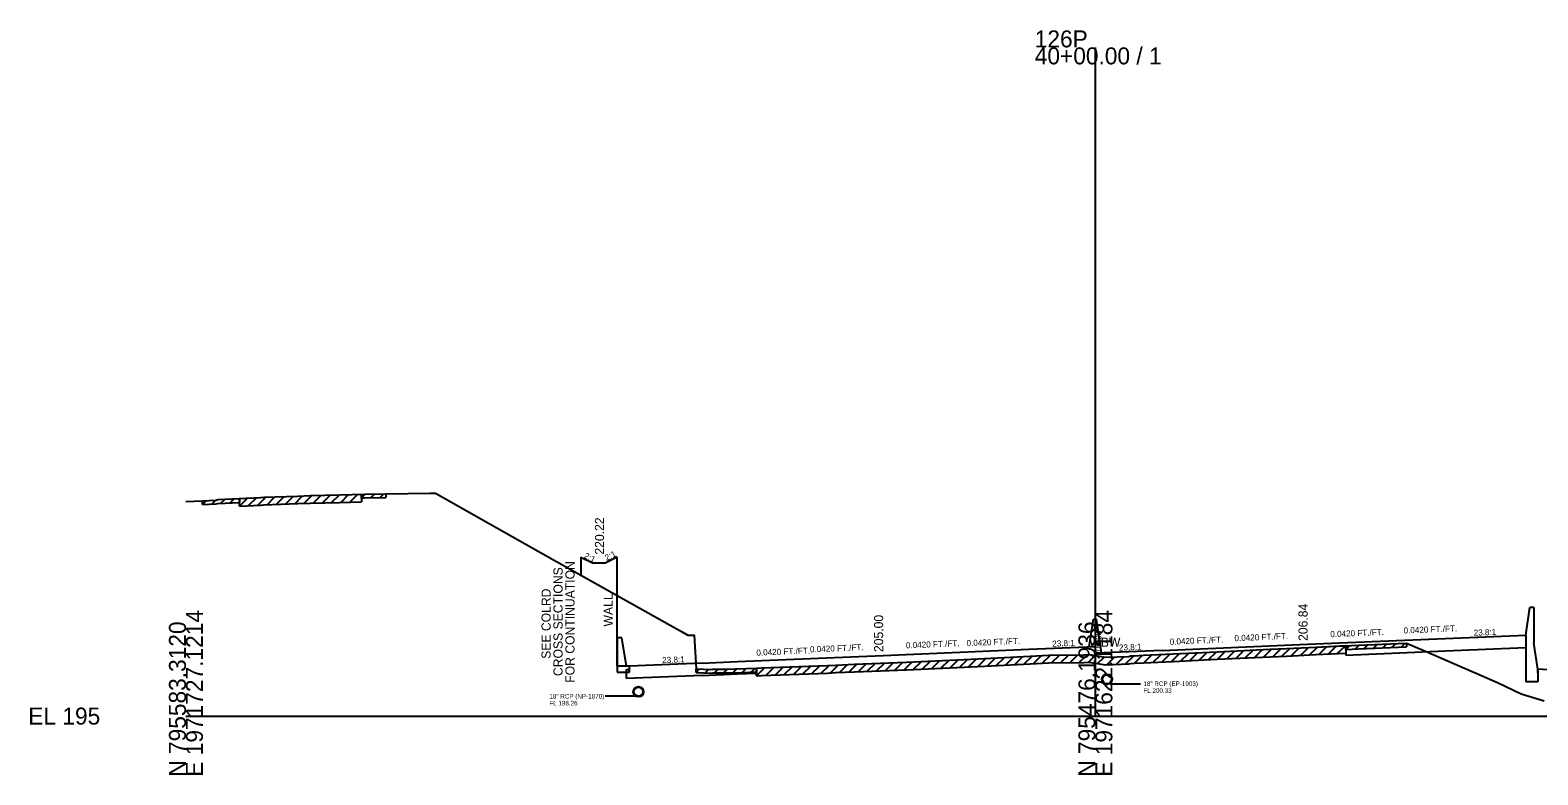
# Model space of a CAD drawing. Extents: x -161 to 1970889, y -4362 to 797231.
# Drawn here: x 974.3 to 1223, y 2490.3 to 2613.1 of the extents above; entities that cross this region are included whole.
import ezdxf

# ---------------------------------------------------------------- set-up
doc = ezdxf.new("R2010")
doc.units = 0
for name, color, linetype in [('RD_GPK_XS_Cell', 7, 'Continuous'), ('RD_XS_Base', 7, 'Continuous'), ('RD_XS_Box', 7, 'Continuous'), ('RD_XS_ExGround', 7, 'Continuous'), ('RD_XS_ExPaveRet', 7, 'Continuous'), ('RD_XS_MedBWall', 7, 'Continuous'), ('RD_XS_Misc_Line', 7, 'Continuous'), ('RD_XS_Pave', 7, 'Continuous'), ('RD_XS_PaveOvlay', 7, 'Continuous'), ('RD_XS_PaveShd', 7, 'Continuous'), ('RD_XS_Pipe', 7, 'Continuous'), ('RD_XS_TieSlope', 7, 'Continuous'), ('RD_XS_TX_Elev_EX', 7, 'Continuous'), ('RD_XS_TX_Elev_PR', 7, 'Continuous'), ('RD_XS_TX_Misc', 7, 'Continuous'), ('RD_XS_TX_MkPT', 7, 'Continuous'), ('RD_XS_TX_Notes', 7, 'Continuous'), ('RD_XS_TX_Profile', 7, 'Continuous'), ('RD_XS_TX_Slope', 7, 'Continuous')]:
    doc.layers.add(name, color=color, linetype=linetype)

msp = doc.modelspace()

# ---------------------------------------------------------------- linework, layer by layer
at = {"layer": 'RD_GPK_XS_Cell'}
for p, q in [((1150, 2500), (1150, 2610.28)), ((1000, 2500), (1150, 2500)), ((1150, 2500), (1300, 2500))]:
    msp.add_line(p, q, dxfattribs=at)
at = {"layer": 'RD_XS_Base'}
for p, q in [((1191.31, 2510.07), (1209, 2510.81)), ((1209, 2510.81), (1221, 2511.32)), ((1072.65, 2507.66), (1073.15, 2507.69)), ((1072.65, 2506.18), (1072.65, 2507.66)), ((1085.16, 2506.71), (1072.65, 2506.18)), ((1073.15, 2507.69), (1073.15, 2508.25)), ((1085.16, 2506.71), (1091, 2506.96)), ((1091, 2506.96), (1094.13, 2507.09)), ((1222.98, 2507.15), (1222.98, 2507.71))]:
    msp.add_line(p, q, dxfattribs=at)
at = {"layer": 'RD_XS_Box'}
for p, q in [((1071.15, 2508.25), (1071.15, 2526.22)), ((1073.15, 2508.25), (1071.15, 2508.25))]:
    msp.add_line(p, q, dxfattribs=at)
at = {"layer": 'RD_XS_ExGround'}
msp.add_lwpolyline([(1000, 2535.38), (1002.74, 2535.49), (1004.91, 2535.61), (1005.28, 2535.69), (1012.31, 2536.06), (1012.83, 2536.09), (1018.44, 2536.29), (1020.51, 2536.36), (1025.32, 2536.49), (1029.45, 2536.6), (1032.97, 2536.65), (1040.23, 2536.76), (1040.86, 2536.76), (1041.16, 2536.75), (1052.53, 2530.34), (1060.65, 2525.75), (1081.74, 2513.94), (1082.77, 2513.36), (1083.82, 2513.36), (1084.13, 2507.81), (1086.6, 2507.69), (1086.92, 2507.73), (1089.09, 2507.75), (1090.65, 2507.77), (1094.23, 2507.9), (1094.95, 2507.93), (1105.84, 2508.35), (1107.2, 2508.41), (1110.25, 2508.54), (1118.83, 2508.9), (1128.37, 2509.32), (1130.63, 2509.42), (1139.26, 2509.86), (1142.34, 2510.02), (1145.11, 2510.08), (1145.43, 2510.04), (1148.11, 2510.11), (1148.99, 2510.13), (1149.54, 2510.05), (1150, 2509.98), (1151.65, 2509.71), (1155.51, 2509.85), (1155.78, 2509.93), (1156.45, 2509.96), (1157.91, 2510.04), (1162.82, 2510.27), (1170.07, 2510.61), (1178.83, 2511.03), (1181.53, 2511.15), (1186.35, 2511.38), (1193.42, 2511.71), (1199.94, 2511.98), (1201.31, 2512.04), (1204.18, 2510.8), (1216.33, 2505.56), (1220.21, 2503.67), (1224.04, 2502.52)], dxfattribs=at)
at = {"layer": 'RD_XS_ExPaveRet'}
for p, q in [((1028.94, 2536.58), (1028.94, 2535.33)), ((1028.94, 2535.96), (1028.94, 2536.58)), ((1028.94, 2536.58), (1028.94, 2535.33)), ((1028.94, 2535.96), (1028.94, 2536.58)), ((1028.94, 2536.58), (1028.94, 2535.33)), ((1028.94, 2535.96), (1028.94, 2536.58)), ((1032.97, 2536.65), (1032.97, 2536.02)), ((1032.97, 2536.65), (1032.97, 2536.02)), ((1032.97, 2536.65), (1032.97, 2536.02)), ((1002.74, 2534.87), (1002.74, 2535.49)), ((1002.74, 2534.87), (1002.74, 2535.49)), ((1002.74, 2534.87), (1002.74, 2535.49)), ((1002.74, 2534.87), (1004.91, 2534.98)), ((1002.74, 2534.87), (1004.91, 2534.98)), ((1002.74, 2534.87), (1004.91, 2534.98)), ((1004.91, 2534.98), (1005.28, 2535.06)), ((1004.91, 2534.98), (1005.28, 2535.06)), ((1004.91, 2534.98), (1005.28, 2535.06)), ((1005.28, 2535.06), (1008.82, 2535.25)), ((1005.28, 2535.06), (1008.82, 2535.25)), ((1005.28, 2535.06), (1008.82, 2535.25)), ((1008.82, 2534.63), (1008.82, 2535.88)), ((1008.82, 2535.88), (1008.82, 2535.25)), ((1008.82, 2534.63), (1008.82, 2535.88)), ((1008.82, 2535.88), (1008.82, 2535.25)), ((1008.82, 2534.63), (1008.82, 2535.88)), ((1008.82, 2535.88), (1008.82, 2535.25)), ((1008.82, 2534.63), (1012.31, 2534.81)), ((1008.82, 2534.63), (1012.31, 2534.81)), ((1008.82, 2534.63), (1012.31, 2534.81)), ((1012.31, 2534.81), (1012.83, 2534.84)), ((1012.31, 2534.81), (1012.83, 2534.84)), ((1012.31, 2534.81), (1012.83, 2534.84)), ((1012.83, 2534.84), (1018.44, 2535.04)), ((1012.83, 2534.84), (1018.44, 2535.04)), ((1012.83, 2534.84), (1018.44, 2535.04)), ((1018.44, 2535.04), (1020.51, 2535.11)), ((1018.44, 2535.04), (1020.51, 2535.11)), ((1018.44, 2535.04), (1020.51, 2535.11)), ((1020.51, 2535.11), (1025.32, 2535.24)), ((1020.51, 2535.11), (1025.32, 2535.24)), ((1020.51, 2535.11), (1025.32, 2535.24)), ((1025.32, 2535.24), (1028.94, 2535.33)), ((1025.32, 2535.24), (1028.94, 2535.33)), ((1025.32, 2535.24), (1028.94, 2535.33)), ((1028.94, 2535.96), (1029.45, 2535.97)), ((1028.94, 2535.96), (1029.45, 2535.97)), ((1028.94, 2535.96), (1029.45, 2535.97)), ((1029.45, 2535.97), (1032.97, 2536.02)), ((1029.45, 2535.97), (1032.97, 2536.02)), ((1029.45, 2535.97), (1032.97, 2536.02)), ((1191.31, 2511.62), (1191.31, 2510.37)), ((1191.31, 2510.99), (1191.31, 2511.62)), ((1201.31, 2512.04), (1201.31, 2511.41)), ((1162.82, 2509.02), (1170.07, 2509.36)), ((1170.07, 2509.36), (1178.83, 2509.78)), ((1178.83, 2509.78), (1181.53, 2509.9)), ((1181.53, 2509.9), (1186.35, 2510.13)), ((1186.35, 2510.13), (1191.31, 2510.37)), ((1191.31, 2510.99), (1193.42, 2511.09)), ((1193.42, 2511.09), (1199.94, 2511.36)), ((1199.94, 2511.36), (1201.31, 2511.41)), ((1084.13, 2507.19), (1084.13, 2507.81)), ((1084.13, 2507.19), (1086.6, 2507.07)), ((1086.6, 2507.07), (1086.92, 2507.11)), ((1086.92, 2507.11), (1089.09, 2507.13)), ((1089.09, 2507.13), (1090.65, 2507.14)), ((1090.65, 2507.14), (1094.13, 2507.27)), ((1094.13, 2506.65), (1094.13, 2507.9)), ((1094.13, 2507.9), (1094.13, 2507.27)), ((1094.13, 2506.65), (1094.23, 2506.65)), ((1094.23, 2506.65), (1094.95, 2506.68)), ((1094.95, 2506.68), (1105.84, 2507.1)), ((1105.84, 2507.1), (1107.2, 2507.16)), ((1107.2, 2507.16), (1110.25, 2507.29)), ((1110.25, 2507.29), (1118.83, 2507.65)), ((1118.83, 2507.65), (1128.37, 2508.07)), ((1128.37, 2508.07), (1130.63, 2508.17)), ((1130.63, 2508.17), (1139.26, 2508.61)), ((1139.26, 2508.61), (1142.34, 2508.77)), ((1142.34, 2508.77), (1145.11, 2508.83)), ((1145.11, 2508.83), (1145.43, 2508.79)), ((1145.43, 2508.79), (1148.11, 2508.86)), ((1148.11, 2508.86), (1148.99, 2508.88)), ((1148.99, 2508.88), (1149.54, 2508.8)), ((1149.54, 2508.8), (1150, 2508.73)), ((1150, 2508.73), (1151.65, 2508.46)), ((1151.65, 2508.46), (1155.51, 2508.6)), ((1155.51, 2508.6), (1155.78, 2508.68)), ((1155.78, 2508.68), (1156.45, 2508.71)), ((1156.45, 2508.71), (1157.91, 2508.79)), ((1157.91, 2508.79), (1162.82, 2509.02))]:
    msp.add_line(p, q, dxfattribs=at)
at = {"layer": 'RD_XS_MedBWall'}
for p, q in [((1221, 2513.36), (1221.67, 2517.9)), ((1222.33, 2517.9), (1221.67, 2517.9)), ((1222.33, 2517.9), (1222.33, 2512.1)), ((1149, 2511.43), (1149.67, 2515.97)), ((1149.67, 2515.97), (1150.17, 2515.97)), ((1151, 2510.42), (1150.17, 2515.97)), ((1071.9, 2512.91), (1071.15, 2512.91)), ((1071.15, 2512.91), (1071.15, 2507.25)), ((1072.65, 2508.25), (1071.9, 2512.91)), ((1221, 2513.36), (1221, 2511.32)), ((1221, 2513.36), (1221, 2505.67)), ((1222.98, 2507.71), (1222.33, 2512.1)), ((1071.15, 2507.25), (1073.15, 2507.25)), ((1073.15, 2508.25), (1072.65, 2508.25)), ((1073.15, 2507.25), (1073.15, 2508.25)), ((1222.98, 2507.71), (1222.98, 2505.67)), ((1222.98, 2505.67), (1221, 2505.67))]:
    msp.add_line(p, q, dxfattribs=at)
at = {"layer": 'RD_XS_Misc_Line'}
for p, q in [((1022.5, 2535.17), (1023.8, 2536.45)), ((1022.5, 2535.17), (1023.8, 2536.45)), ((1022.5, 2535.17), (1023.8, 2536.45)), ((1024.02, 2535.21), (1025.32, 2536.49)), ((1024.02, 2535.21), (1025.32, 2536.49)), ((1024.02, 2535.21), (1025.32, 2536.49)), ((1025.54, 2535.25), (1026.84, 2536.53)), ((1025.54, 2535.25), (1026.84, 2536.53)), ((1025.54, 2535.25), (1026.84, 2536.53)), ((1027.06, 2535.29), (1028.36, 2536.57)), ((1027.06, 2535.29), (1028.36, 2536.57)), ((1027.06, 2535.29), (1028.36, 2536.57)), ((1028.94, 2535.96), (1029.58, 2536.6)), ((1028.94, 2535.96), (1029.58, 2536.6)), ((1028.94, 2535.96), (1029.58, 2536.6)), ((1030.46, 2535.99), (1031.1, 2536.62)), ((1030.46, 2535.99), (1031.1, 2536.62)), ((1030.46, 2535.99), (1031.1, 2536.62)), ((1031.98, 2536.01), (1032.62, 2536.64)), ((1031.98, 2536.01), (1032.62, 2536.64)), ((1031.98, 2536.01), (1032.62, 2536.64)), ((1002.74, 2534.87), (1003.41, 2535.53)), ((1002.74, 2534.87), (1003.41, 2535.53)), ((1002.74, 2534.87), (1003.41, 2535.53)), ((1004.26, 2534.95), (1004.93, 2535.61)), ((1004.26, 2534.95), (1004.93, 2535.61)), ((1004.26, 2534.95), (1004.93, 2535.61)), ((1005.78, 2535.09), (1006.45, 2535.75)), ((1005.78, 2535.09), (1006.45, 2535.75)), ((1005.78, 2535.09), (1006.45, 2535.75)), ((1007.3, 2535.17), (1007.97, 2535.83)), ((1007.3, 2535.17), (1007.97, 2535.83)), ((1007.3, 2535.17), (1007.97, 2535.83)), ((1008.82, 2534.63), (1010.16, 2535.95)), ((1008.82, 2534.63), (1010.16, 2535.95)), ((1008.82, 2534.63), (1010.16, 2535.95)), ((1010.34, 2534.71), (1011.68, 2536.03)), ((1010.34, 2534.71), (1011.68, 2536.03)), ((1010.34, 2534.71), (1011.68, 2536.03)), ((1011.86, 2534.79), (1013.19, 2536.1)), ((1011.86, 2534.79), (1013.19, 2536.1)), ((1011.86, 2534.79), (1013.19, 2536.1)), ((1013.38, 2534.86), (1014.69, 2536.16)), ((1013.38, 2534.86), (1014.69, 2536.16)), ((1013.38, 2534.86), (1014.69, 2536.16)), ((1014.9, 2534.91), (1016.21, 2536.21)), ((1014.9, 2534.91), (1016.21, 2536.21)), ((1014.9, 2534.91), (1016.21, 2536.21)), ((1016.42, 2534.97), (1017.73, 2536.27)), ((1016.42, 2534.97), (1017.73, 2536.27)), ((1016.42, 2534.97), (1017.73, 2536.27)), ((1017.94, 2535.02), (1019.25, 2536.32)), ((1017.94, 2535.02), (1019.25, 2536.32)), ((1017.94, 2535.02), (1019.25, 2536.32)), ((1019.46, 2535.08), (1020.77, 2536.37)), ((1019.46, 2535.08), (1020.77, 2536.37)), ((1019.46, 2535.08), (1020.77, 2536.37)), ((1020.98, 2535.13), (1022.28, 2536.41)), ((1020.98, 2535.13), (1022.28, 2536.41)), ((1020.98, 2535.13), (1022.28, 2536.41)), ((1189.9, 2510.3), (1191.23, 2511.61)), ((1191.31, 2510.99), (1191.98, 2511.65)), ((1192.83, 2511.06), (1193.5, 2511.72)), ((1194.35, 2511.13), (1195.01, 2511.78)), ((1195.87, 2511.19), (1196.53, 2511.84)), ((1197.39, 2511.25), (1198.05, 2511.91)), ((1198.91, 2511.32), (1199.57, 2511.97)), ((1200.43, 2511.38), (1201.09, 2512.03)), ((1123.01, 2507.83), (1124.34, 2509.14)), ((1124.53, 2507.9), (1125.86, 2509.21)), ((1126.05, 2507.97), (1127.38, 2509.28)), ((1127.57, 2508.03), (1128.9, 2509.34)), ((1129.09, 2508.1), (1130.42, 2509.42)), ((1130.61, 2508.17), (1131.95, 2509.49)), ((1132.13, 2508.25), (1133.47, 2509.57)), ((1133.65, 2508.33), (1134.99, 2509.64)), ((1135.17, 2508.4), (1136.51, 2509.72)), ((1136.69, 2508.48), (1138.03, 2509.8)), ((1138.21, 2508.56), (1139.55, 2509.87)), ((1139.73, 2508.63), (1141.07, 2509.95)), ((1141.25, 2508.71), (1142.58, 2510.02)), ((1142.77, 2508.77), (1144.07, 2510.05)), ((1144.29, 2508.81), (1145.54, 2510.04)), ((1145.81, 2508.8), (1147.12, 2510.09)), ((1147.33, 2508.84), (1148.63, 2510.12)), ((1148.85, 2508.88), (1149.97, 2509.98)), ((1150.37, 2508.66), (1151.46, 2509.74)), ((1151.89, 2508.47), (1153.21, 2509.77)), ((1153.41, 2508.52), (1154.73, 2509.82)), ((1154.94, 2508.58), (1156.33, 2509.96)), ((1156.46, 2508.71), (1157.79, 2510.03)), ((1157.98, 2508.79), (1159.31, 2510.1)), ((1159.5, 2508.86), (1160.83, 2510.18)), ((1161.02, 2508.93), (1162.35, 2510.25)), ((1162.54, 2509.01), (1163.87, 2510.32)), ((1164.06, 2509.08), (1165.39, 2510.39)), ((1165.58, 2509.15), (1166.91, 2510.46)), ((1167.1, 2509.22), (1168.43, 2510.54)), ((1168.62, 2509.3), (1169.95, 2510.61)), ((1170.14, 2509.37), (1171.47, 2510.68)), ((1171.66, 2509.44), (1172.99, 2510.75)), ((1173.18, 2509.51), (1174.51, 2510.82)), ((1174.7, 2509.58), (1176.03, 2510.89)), ((1176.22, 2509.65), (1177.55, 2510.96)), ((1177.74, 2509.72), (1179.07, 2511.04)), ((1179.26, 2509.79), (1180.59, 2511.11)), ((1180.78, 2509.86), (1182.11, 2511.18)), ((1182.3, 2509.94), (1183.63, 2511.25)), ((1183.82, 2510.01), (1185.15, 2511.32)), ((1185.34, 2510.08), (1186.67, 2511.4)), ((1186.86, 2510.16), (1188.19, 2511.47)), ((1188.38, 2510.23), (1189.71, 2511.54)), ((1084.13, 2507.19), (1084.73, 2507.78)), ((1085.65, 2507.11), (1086.25, 2507.71)), ((1087.17, 2507.11), (1087.81, 2507.74)), ((1088.69, 2507.13), (1089.33, 2507.76)), ((1090.21, 2507.14), (1090.85, 2507.77)), ((1091.73, 2507.18), (1092.39, 2507.83)), ((1093.25, 2507.24), (1093.91, 2507.89)), ((1094.13, 2506.65), (1095.45, 2507.95)), ((1095.65, 2506.71), (1096.97, 2508.01)), ((1097.17, 2506.77), (1098.49, 2508.07)), ((1098.69, 2506.83), (1100.01, 2508.13)), ((1100.21, 2506.88), (1101.53, 2508.19)), ((1101.73, 2506.94), (1103.05, 2508.25)), ((1103.25, 2507), (1104.57, 2508.31)), ((1104.77, 2507.06), (1106.09, 2508.36)), ((1106.29, 2507.12), (1107.61, 2508.43)), ((1107.81, 2507.19), (1109.13, 2508.49)), ((1109.33, 2507.25), (1110.65, 2508.56)), ((1110.85, 2507.32), (1112.17, 2508.62)), ((1112.37, 2507.38), (1113.69, 2508.69)), ((1113.89, 2507.44), (1115.21, 2508.75)), ((1115.41, 2507.51), (1116.73, 2508.81)), ((1116.93, 2507.57), (1118.25, 2508.88)), ((1118.45, 2507.63), (1119.78, 2508.94)), ((1119.97, 2507.7), (1121.3, 2509.01)), ((1121.49, 2507.77), (1122.82, 2509.08))]:
    msp.add_line(p, q, dxfattribs=at)
at = {"layer": 'RD_XS_Pave'}
for p, q in [((1161, 2510.84), (1185, 2511.84)), ((1185, 2511.84), (1209, 2512.85)), ((1091, 2509), (1115, 2510)), ((1115, 2510), (1139, 2511.01)), ((1085.16, 2508.75), (1091, 2509))]:
    msp.add_line(p, q, dxfattribs=at)
at = {"layer": 'RD_XS_PaveOvlay'}
for p, q in [((1186.35, 2511.38), (1191.31, 2511.62)), ((1191.31, 2511.62), (1191.31, 2510.07)), ((1118.83, 2508.9), (1128.37, 2509.32)), ((1128.37, 2509.32), (1130.63, 2509.42)), ((1130.63, 2509.42), (1139.26, 2509.86)), ((1139.26, 2509.86), (1142.34, 2510.02)), ((1142.34, 2510.02), (1145.11, 2510.08)), ((1145.11, 2510.08), (1145.43, 2510.04)), ((1145.43, 2510.04), (1148.11, 2510.11)), ((1148.11, 2510.11), (1148.99, 2510.13)), ((1148.99, 2510.13), (1149.54, 2510.05)), ((1149.54, 2510.05), (1150, 2509.98)), ((1150, 2509.98), (1151.65, 2509.71)), ((1151.65, 2509.71), (1155.51, 2509.85)), ((1155.51, 2509.85), (1155.78, 2509.93)), ((1155.78, 2509.93), (1156.45, 2509.96)), ((1156.45, 2509.96), (1157.91, 2510.04)), ((1157.91, 2510.04), (1162.82, 2510.27)), ((1162.82, 2510.27), (1170.07, 2510.61)), ((1170.07, 2510.61), (1178.83, 2511.03)), ((1178.83, 2511.03), (1181.53, 2511.15)), ((1181.53, 2511.15), (1186.35, 2511.38)), ((1094.13, 2507.9), (1094.23, 2507.9)), ((1094.13, 2507.9), (1094.13, 2507.09)), ((1094.23, 2507.9), (1094.95, 2507.93)), ((1094.95, 2507.93), (1105.84, 2508.35)), ((1105.84, 2508.35), (1107.2, 2508.41)), ((1107.2, 2508.41), (1110.25, 2508.54)), ((1110.25, 2508.54), (1118.83, 2508.9))]:
    msp.add_line(p, q, dxfattribs=at)
at = {"layer": 'RD_XS_PaveShd'}
for p, q in [((1209, 2512.85), (1221, 2513.36)), ((1139, 2511.01), (1150, 2511.47)), ((1150, 2510.26), (1150, 2511.47)), ((1161, 2510.84), (1150, 2510.37)), ((1085.16, 2508.75), (1073.15, 2508.25)), ((1233.54, 2507.01), (1222.98, 2507.71))]:
    msp.add_line(p, q, dxfattribs=at)
at = {"layer": 'RD_XS_Pipe'}
for p, q in [((1152.42, 2505.33), (1157.42, 2505.33)), ((1074.14, 2503.26), (1069.14, 2503.26))]:
    msp.add_line(p, q, dxfattribs=at)
for centre, radius in [((1151.92, 2506.08), 0.85), ((1151.92, 2506.08), 0.75), ((1074.64, 2504.01), 0.85), ((1074.64, 2504.01), 0.75)]:
    msp.add_circle(centre, radius, dxfattribs=at)
at = {"layer": 'RD_XS_TieSlope'}
for p, q in [((1065.15, 2526.22), (1067.15, 2525.22)), ((1065.15, 2526.22), (1065.15, 2523.23)), ((1069.15, 2525.22), (1067.15, 2525.22)), ((1071.15, 2526.22), (1069.15, 2525.22))]:
    msp.add_line(p, q, dxfattribs=at)

# ---------------------------------------------------------------- texts
at = {"layer": 'RD_GPK_XS_Cell'}
for s, p in [('126P', (1140, 2610.28)), ('40+00.00 / 1', (1140, 2607.48)), ('EL 195', (974, 2498.6))]:
    msp.add_text(s, height=2.8, dxfattribs=at).set_placement(p)
for s, p in [('E 1971727.1214', (1002.8, 2490)), ('E 1971622.1184', (1152.8, 2490)), ('N 795583.3120', (1000, 2490)), ('N 795476.1936', (1150, 2490))]:
    msp.add_text(s, height=2.8, rotation=90, dxfattribs=at).set_placement(p)
at = {"layer": 'RD_XS_Pipe'}
for s, p in [('18" RCP (EP-1903)', (1157.92, 2504.96)), ('FL 200.33', (1157.92, 2503.83)), ('18" RCP (NP-1870)', (1059.94, 2502.89)), ('FL 198.26', (1059.94, 2501.76))]:
    msp.add_text(s, height=0.75, dxfattribs=at).set_placement(p)
at = {"layer": 'RD_XS_TX_Elev_EX'}
msp.add_text('204.98', height=1, rotation=90, dxfattribs=at).set_placement((1151, 2509.98))
at = {"layer": 'RD_XS_TX_Elev_PR'}
for s, p in [(' 205.00', (1115, 2510)), (' 206.84', (1185, 2511.84))]:
    msp.add_text(s, height=1.5, rotation=90, dxfattribs=at).set_placement(p)
at = {"layer": 'RD_XS_TX_Misc'}
msp.add_text('220.22', height=1.5, rotation=90, dxfattribs=at).set_placement((1068.96, 2526.63))
at = {"layer": 'RD_XS_TX_MkPT'}
msp.add_text('WBW', height=1.5, dxfattribs=at).set_placement((1149, 2511.43))
at = {"layer": 'RD_XS_TX_Notes'}
for s, p in [('CROSS SECTIONS', (1062.12, 2506.6)), ('FOR CONTINUATION', (1064.09, 2505.49)), ('SEE COLRD', (1060.15, 2509.44)), ('WALL', (1070.41, 2514.77))]:
    msp.add_text(s, height=1.5, rotation=90, dxfattribs=at).set_placement(p)
at = {"layer": 'RD_XS_TX_Profile'}
for rotation, p in [(2.405, (1212.41, 2513.24)), (2.405, (1142.91, 2511.43)), (2.405, (1153.91, 2510.79)), (2.4033, (1078.57, 2508.72))]:
    msp.add_text('23.8:1', height=1, rotation=rotation, dxfattribs=at).set_placement(p)
at = {"layer": 'RD_XS_TX_Slope'}
for s, rotation, p in [('2:1', 333.4349, (1065.57, 2526.13)), ('2:1', 26.5651, (1069.39, 2525.58)), ('0.0420 FT./FT.', 2.405, (1188.77, 2513)), ('0.0420 FT./FT.', 2.405, (1200.85, 2513.61)), ('0.0420 FT./FT.', 2.4033, (1102.95, 2510.5)), ('0.0420 FT./FT.', 2.405, (1118.77, 2511.16)), ('0.0420 FT./FT.', 2.405, (1128.77, 2511.53)), ('0.0420 FT./FT.', 2.405, (1162.28, 2511.76)), ('0.0420 FT./FT.', 2.405, (1172.96, 2512.34)), ('0.0420 FT./FT.', 2.405, (1094.11, 2509.95))]:
    msp.add_text(s, height=1, rotation=rotation, dxfattribs=at).set_placement(p)

doc.saveas('drawing.dxf')
